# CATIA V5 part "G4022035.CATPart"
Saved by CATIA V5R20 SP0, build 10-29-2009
Part number: G4022035
Revision: 7
Definition: design
Nomenclature: G4022035
Source: made
Description: NOT SPECIFIED
Bounding box of the stored display mesh (mm): x -15 to 35, y -16 to 16, z -16 to 16
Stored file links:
  C:\Users\Raffaele\Desktop\3D X SITO CF\BOLEX\26-BUSH REF 402\G4022035.CATPart
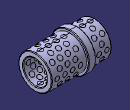
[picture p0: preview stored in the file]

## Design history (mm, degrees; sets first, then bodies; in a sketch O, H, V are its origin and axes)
Body1 "MANIFOLD_SOLID_BREP #11591" (main body)
  Solid1: solid without history
Body2 "MANIFOLD_SOLID_BREP #11742"
  Solid2: solid without history
Body3 "MANIFOLD_SOLID_BREP #11893"
  Solid3: solid without history
Body4 "MANIFOLD_SOLID_BREP #12044"
  Solid4: solid without history
Body5 "MANIFOLD_SOLID_BREP #12195"
  Solid5: solid without history
Body6 "MANIFOLD_SOLID_BREP #12344"
  Solid6: solid without history
Body7 "MANIFOLD_SOLID_BREP #12493"
  Solid7: solid without history
Body8 "MANIFOLD_SOLID_BREP #12642"
  Solid8: solid without history
Body9 "MANIFOLD_SOLID_BREP #12791"
  Solid9: solid without history
Body10 "MANIFOLD_SOLID_BREP #12940"
  Solid10: solid without history
Body11 "MANIFOLD_SOLID_BREP #13089"
  Solid11: solid without history
Body12 "MANIFOLD_SOLID_BREP #13238"
  Solid12: solid without history
Body13 "MANIFOLD_SOLID_BREP #13387"
  Solid13: solid without history
Body14 "MANIFOLD_SOLID_BREP #13536"
  Solid14: solid without history
Body15 "MANIFOLD_SOLID_BREP #13685"
  Solid15: solid without history
Body16 "MANIFOLD_SOLID_BREP #13834"
  Solid16: solid without history
Body17 "MANIFOLD_SOLID_BREP #13983"
  Solid17: solid without history
Body18 "MANIFOLD_SOLID_BREP #14132"
  Solid18: solid without history
Body19 "MANIFOLD_SOLID_BREP #14281"
  Solid19: solid without history
Body20 "MANIFOLD_SOLID_BREP #14430"
  Solid20: solid without history
Body21 "MANIFOLD_SOLID_BREP #14579"
  Solid21: solid without history
Body22 "MANIFOLD_SOLID_BREP #14728"
  Solid22: solid without history
Body23 "MANIFOLD_SOLID_BREP #14877"
  Solid23: solid without history
Body24 "MANIFOLD_SOLID_BREP #15026"
  Solid24: solid without history
Body25 "MANIFOLD_SOLID_BREP #15175"
  Solid25: solid without history
Body26 "MANIFOLD_SOLID_BREP #15324"
  Solid26: solid without history
Body27 "MANIFOLD_SOLID_BREP #15473"
  Solid27: solid without history
Body28 "MANIFOLD_SOLID_BREP #15622"
  Solid28: solid without history
Body29 "MANIFOLD_SOLID_BREP #15771"
  Solid29: solid without history
Body30 "MANIFOLD_SOLID_BREP #15920"
  Solid30: solid without history
Body31 "MANIFOLD_SOLID_BREP #16069"
  Solid31: solid without history
Body32 "MANIFOLD_SOLID_BREP #16218"
  Solid32: solid without history
Body33 "MANIFOLD_SOLID_BREP #16367"
  Solid33: solid without history
Body34 "MANIFOLD_SOLID_BREP #16516"
  Solid34: solid without history
Body35 "MANIFOLD_SOLID_BREP #16667"
  Solid35: solid without history
Body36 "MANIFOLD_SOLID_BREP #16818"
  Solid36: solid without history
Body37 "MANIFOLD_SOLID_BREP #16967"
  Solid37: solid without history
Body38 "MANIFOLD_SOLID_BREP #17116"
  Solid38: solid without history
Body39 "MANIFOLD_SOLID_BREP #17265"
  Solid39: solid without history
Body40 "MANIFOLD_SOLID_BREP #17414"
  Solid40: solid without history
Body41 "MANIFOLD_SOLID_BREP #17563"
  Solid41: solid without history
Body42 "MANIFOLD_SOLID_BREP #17712"
  Solid42: solid without history
Body43 "MANIFOLD_SOLID_BREP #17861"
  Solid43: solid without history
Body44 "MANIFOLD_SOLID_BREP #18010"
  Solid44: solid without history
Body45 "MANIFOLD_SOLID_BREP #18159"
  Solid45: solid without history
Body46 "MANIFOLD_SOLID_BREP #18308"
  Solid46: solid without history
Body47 "MANIFOLD_SOLID_BREP #18457"
  Solid47: solid without history
Body48 "MANIFOLD_SOLID_BREP #18606"
  Solid48: solid without history
Body49 "MANIFOLD_SOLID_BREP #18755"
  Solid49: solid without history
Body50 "MANIFOLD_SOLID_BREP #18904"
  Solid50: solid without history
Body51 "MANIFOLD_SOLID_BREP #19053"
  Solid51: solid without history
Body52 "MANIFOLD_SOLID_BREP #19202"
  Solid52: solid without history
Body53 "MANIFOLD_SOLID_BREP #19351"
  Solid53: solid without history
Body54 "MANIFOLD_SOLID_BREP #19500"
  Solid54: solid without history
Body55 "MANIFOLD_SOLID_BREP #19649"
  Solid55: solid without history
Body56 "MANIFOLD_SOLID_BREP #19800"
  Solid56: solid without history
Body57 "MANIFOLD_SOLID_BREP #19951"
  Solid57: solid without history
Body58 "MANIFOLD_SOLID_BREP #20102"
  Solid58: solid without history
Body59 "MANIFOLD_SOLID_BREP #20253"
  Solid59: solid without history
Body60 "MANIFOLD_SOLID_BREP #20402"
  Solid60: solid without history
Body61 "MANIFOLD_SOLID_BREP #20551"
  Solid61: solid without history
Body62 "MANIFOLD_SOLID_BREP #20700"
  Solid62: solid without history
Body63 "MANIFOLD_SOLID_BREP #20849"
  Solid63: solid without history
Body64 "MANIFOLD_SOLID_BREP #20998"
  Solid64: solid without history
Body65 "MANIFOLD_SOLID_BREP #21147"
  Solid65: solid without history
Body66 "MANIFOLD_SOLID_BREP #21296"
  Solid66: solid without history
Body67 "MANIFOLD_SOLID_BREP #21445"
  Solid67: solid without history
Body68 "MANIFOLD_SOLID_BREP #21594"
  Solid68: solid without history
Body69 "MANIFOLD_SOLID_BREP #21743"
  Solid69: solid without history
Body70 "MANIFOLD_SOLID_BREP #21892"
  Solid70: solid without history
Body71 "MANIFOLD_SOLID_BREP #22041"
  Solid71: solid without history
Body72 "MANIFOLD_SOLID_BREP #22190"
  Solid72: solid without history
Body73 "MANIFOLD_SOLID_BREP #22341"
  Solid73: solid without history
Body74 "MANIFOLD_SOLID_BREP #22492"
  Solid74: solid without history
Body75 "MANIFOLD_SOLID_BREP #22641"
  Solid75: solid without history
Body76 "MANIFOLD_SOLID_BREP #22790"
  Solid76: solid without history
Body77 "MANIFOLD_SOLID_BREP #22939"
  Solid77: solid without history
Body78 "MANIFOLD_SOLID_BREP #23088"
  Solid78: solid without history
Body79 "MANIFOLD_SOLID_BREP #23237"
  Solid79: solid without history
Body80 "MANIFOLD_SOLID_BREP #23386"
  Solid80: solid without history
Body81 "MANIFOLD_SOLID_BREP #23535"
  Solid81: solid without history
